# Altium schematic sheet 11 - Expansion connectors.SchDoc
size B; CompanyName: Microchip Technology Inc.; Organization: Microchip Technology; Address1: 2355 West Chandler Blvd.; Address2: Chandler, AZ  85224; Address4: USA; DocumentNumber: 11; SheetNumber: 11; SheetTotal: 13; SheetTitle: Expansion connectors
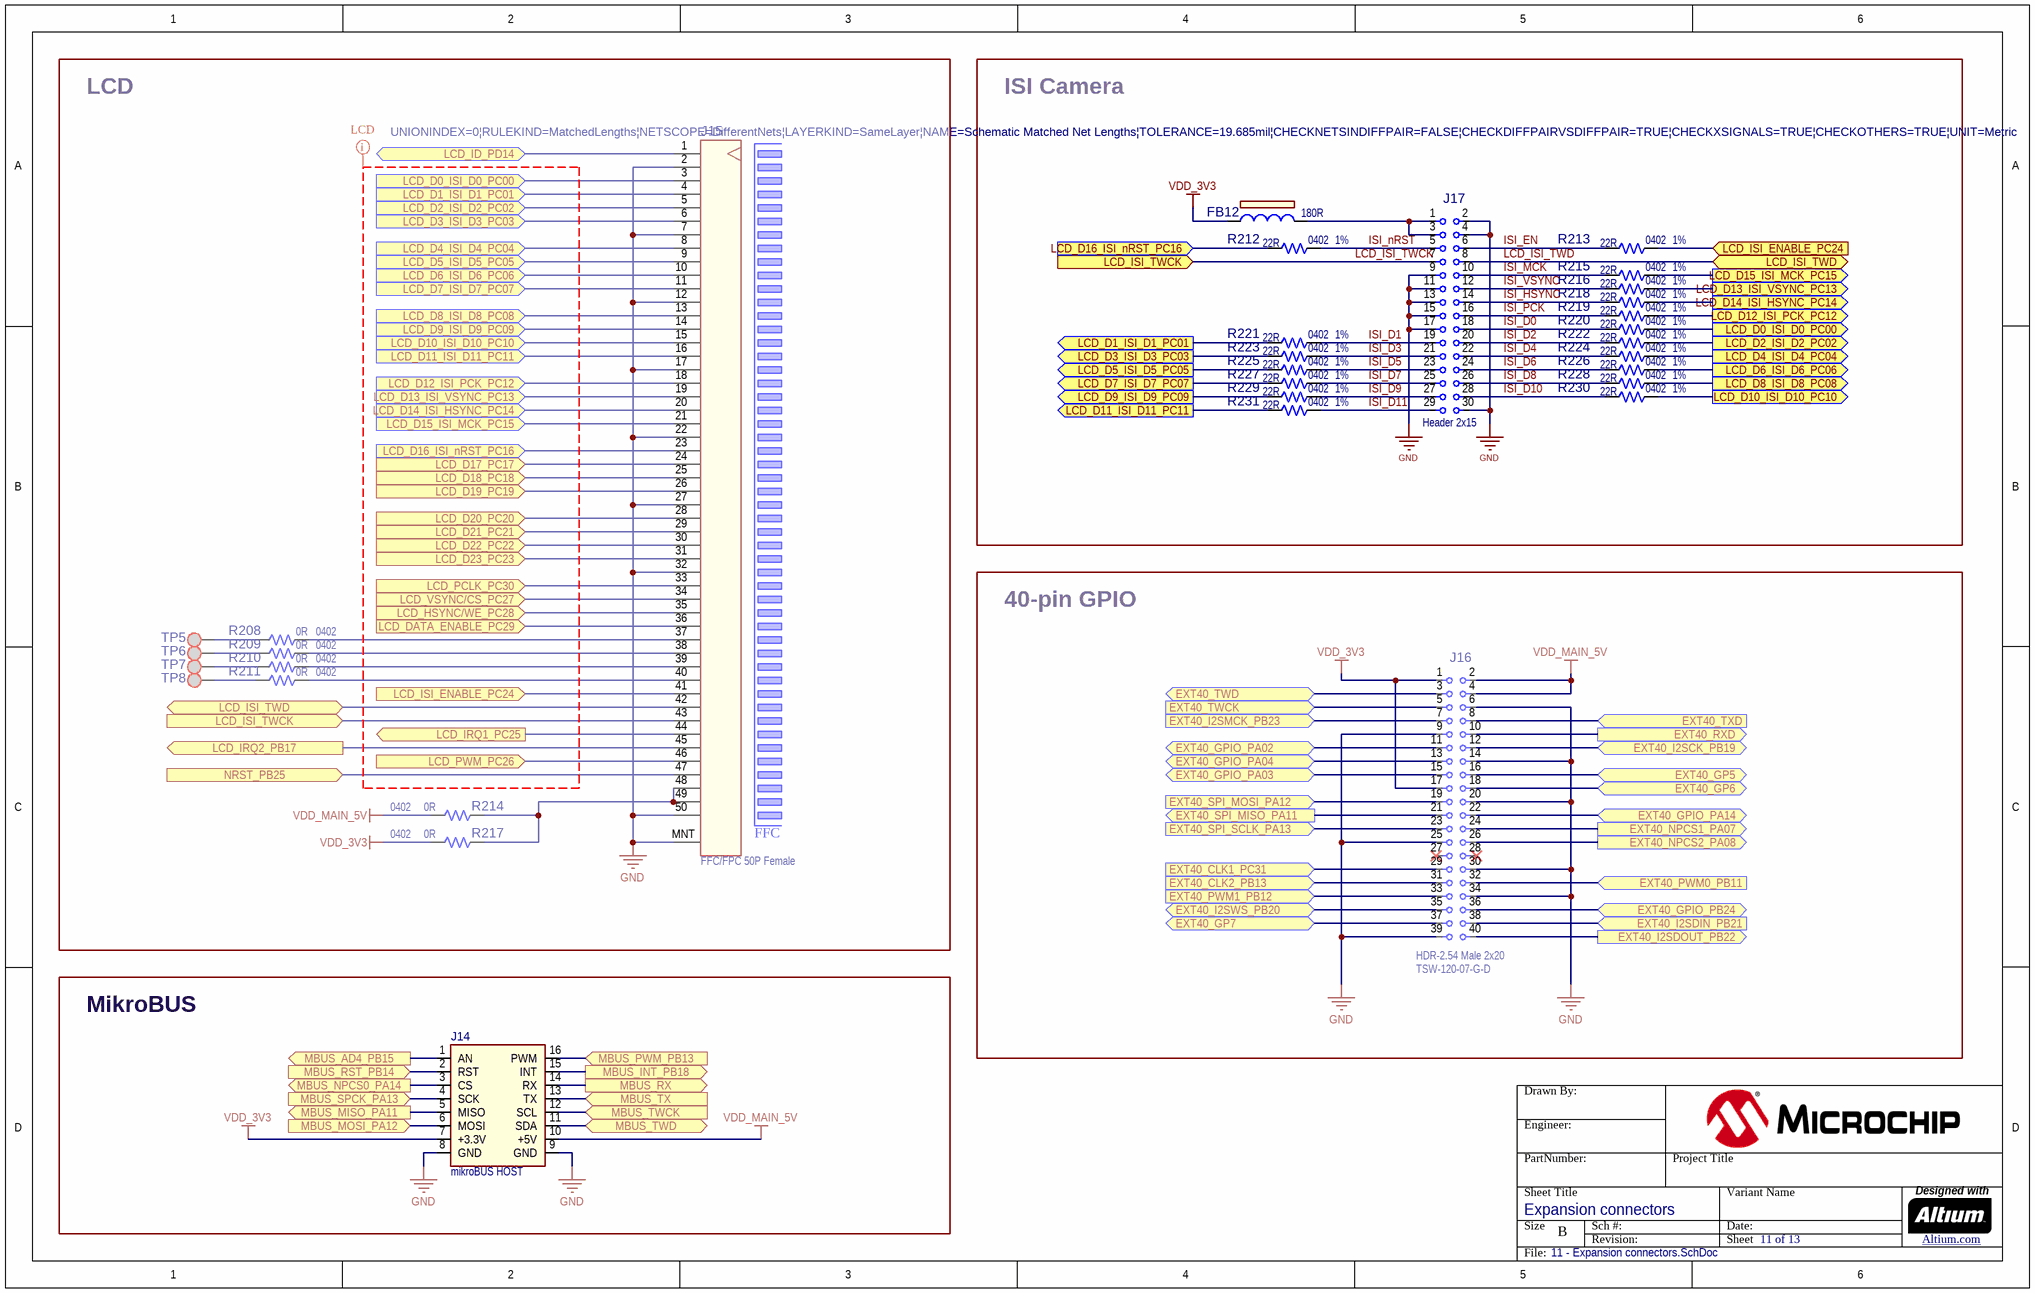
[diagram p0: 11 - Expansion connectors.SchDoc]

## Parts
?  (no value)  (graphical)
FB12  value 180R  [IND_C_0603]  (hidden comment: Ferrite Bead)
J14  value mikroBUS HOST  [SOCKET_mikroBUS_F_2.54_2x8_V_25.4x21]  (hidden comment: SOCKET mikroBUS HOST)
J15  value FFC/FPC 50P Female  [CON_FFC_0.5_FEMALE_1X50_SMD_OMR_XF2M-5015-1A]  (hidden comment: CON FFC 1x50 Mount)
J16  value HDR-2.54 Male 2x20  Manufacturer Part Number 1: TSW-120-07-G-D  [HDR_M_2.54_2x20]  (hidden comment: Header 2x20)
J17  Header 2x15  [HDR_M_2.54_2x15]
R208  value 0R  Package: 0402  [RES_C_0402]  (hidden comment: Resistor)
R209  value 0R  Package: 0402  [RES_C_0402]  (hidden comment: Resistor)
R210  value 0R  Package: 0402  [RES_C_0402]  (hidden comment: Resistor)
R211  value 0R  Package: 0402  [RES_C_0402]  (hidden comment: Resistor)
R212  value 22R  Package: 0402  Tolerance: 1%  [RES_C_0402]  (hidden comment: Resistor)
R213  value 22R  Package: 0402  Tolerance: 1%  [RES_C_0402]  (hidden comment: Resistor)
R214  value 0R  Package: 0402  [RES_C_0402]  (hidden comment: Resistor)
R215  value 22R  Package: 0402  Tolerance: 1%  [RES_C_0402]  (hidden comment: Resistor)
R216  value 22R  Package: 0402  Tolerance: 1%  [RES_C_0402]  (hidden comment: Resistor)
R217  value 0R  Package: 0402  [RES_C_0402]  (hidden comment: Resistor)
R218  value 22R  Package: 0402  Tolerance: 1%  [RES_C_0402]  (hidden comment: Resistor)
R219  value 22R  Package: 0402  Tolerance: 1%  [RES_C_0402]  (hidden comment: Resistor)
R220  value 22R  Package: 0402  Tolerance: 1%  [RES_C_0402]  (hidden comment: Resistor)
R221  value 22R  Package: 0402  Tolerance: 1%  [RES_C_0402]  (hidden comment: Resistor)
R222  value 22R  Package: 0402  Tolerance: 1%  [RES_C_0402]  (hidden comment: Resistor)
R223  value 22R  Package: 0402  Tolerance: 1%  [RES_C_0402]  (hidden comment: Resistor)
R224  value 22R  Package: 0402  Tolerance: 1%  [RES_C_0402]  (hidden comment: Resistor)
R225  value 22R  Package: 0402  Tolerance: 1%  [RES_C_0402]  (hidden comment: Resistor)
R226  value 22R  Package: 0402  Tolerance: 1%  [RES_C_0402]  (hidden comment: Resistor)
R227  value 22R  Package: 0402  Tolerance: 1%  [RES_C_0402]  (hidden comment: Resistor)
R228  value 22R  Package: 0402  Tolerance: 1%  [RES_C_0402]  (hidden comment: Resistor)
R229  value 22R  Package: 0402  Tolerance: 1%  [RES_C_0402]  (hidden comment: Resistor)
R230  value 22R  Package: 0402  Tolerance: 1%  [RES_C_0402]  (hidden comment: Resistor)
R231  value 22R  Package: 0402  Tolerance: 1%  [RES_C_0402]  (hidden comment: Resistor)
TP5  SMD Test Point  [TP_1x1_SMD]  (value not drawn)  (no BOM)
TP6  SMD Test Point  [TP_1x1_SMD]  (value not drawn)  (no BOM)
TP7  SMD Test Point  [TP_1x1_SMD]  (value not drawn)  (no BOM)
TP8  SMD Test Point  [TP_1x1_SMD]  (value not drawn)  (no BOM)

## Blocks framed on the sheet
LCD: J15 R208-R211 R214 R217 TP5-TP8
ISI Camera: FB12 J17 R212 R213 R215 R216 R218-R231
40-pin GPIO: J16
MikroBUS: J14

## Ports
EXT40_CLK1_PC31 (in), EXT40_CLK2_PB13 (in), EXT40_GP5 (bidir), EXT40_GP6 (bidir), EXT40_GP7 (bidir), EXT40_GPIO_PA02 (bidir), EXT40_GPIO_PA03 (bidir), EXT40_GPIO_PA04 (bidir), EXT40_GPIO_PA14 (bidir), EXT40_GPIO_PB24 (bidir), EXT40_I2SCK_PB19 (bidir), EXT40_I2SDIN_PB21 (in), EXT40_I2SDOUT_PB22 (out), EXT40_I2SMCK_PB23 (in), EXT40_I2SWS_PB20 (bidir), EXT40_NPCS1_PA07 (out), EXT40_NPCS2_PA08 (out), EXT40_PWM0_PB11 (in), EXT40_PWM1_PB12 (in), EXT40_RXD (out), EXT40_SPI_MISO_PA11 (out), EXT40_SPI_MOSI_PA12 (in), EXT40_SPI_SCLK_PA13 (in), EXT40_TWCK (in), EXT40_TWD (bidir), EXT40_TXD (in), LCD_D0_ISI_D0_PC00 (in), LCD_D0_ISI_D0_PC00 (out), LCD_D1_ISI_D1_PC01 (in), LCD_D1_ISI_D1_PC01 (out), LCD_D2_ISI_D2_PC02 (in), LCD_D2_ISI_D2_PC02 (out), LCD_D3_ISI_D3_PC03 (in), LCD_D3_ISI_D3_PC03 (out), LCD_D4_ISI_D4_PC04 (in), LCD_D4_ISI_D4_PC04 (out), LCD_D5_ISI_D5_PC05 (in), LCD_D5_ISI_D5_PC05 (out), LCD_D6_ISI_D6_PC06 (in), LCD_D6_ISI_D6_PC06 (out), LCD_D7_ISI_D7_PC07 (in), LCD_D7_ISI_D7_PC07 (out), LCD_D8_ISI_D8_PC08 (in), LCD_D8_ISI_D8_PC08 (out), LCD_D9_ISI_D9_PC09 (in), LCD_D9_ISI_D9_PC09 (out), LCD_D10_ISI_D10_PC10 (in), LCD_D10_ISI_D10_PC10 (out), LCD_D11_ISI_D11_PC11 (in), LCD_D11_ISI_D11_PC11 (out), LCD_D12_ISI_PCK_PC12 (in), LCD_D12_ISI_PCK_PC12 (out), LCD_D13_ISI_VSYNC_PC13 (in), LCD_D13_ISI_VSYNC_PC13 (out), LCD_D14_ISI_HSYNC_PC14 (in), LCD_D14_ISI_HSYNC_PC14 (out), LCD_D15_ISI_MCK_PC15 (in), LCD_D15_ISI_MCK_PC15 (out), LCD_D16_ISI_nRST_PC16 (in), LCD_D17_PC17 (in), LCD_D18_PC18 (in), LCD_D19_PC19 (in), LCD_D20_PC20 (in), LCD_D21_PC21 (in), LCD_D22_PC22 (in), LCD_D23_PC23 (in), LCD_DATA_ENABLE_PC29 (in), LCD_HSYNC/WE_PC28 (in), LCD_ID_PD14 (bidir), LCD_IRQ1_PC25 (out), LCD_IRQ2_PB17 (out), LCD_ISI_ENABLE_PC24 (in), LCD_ISI_TWCK (in), LCD_ISI_TWD (bidir), LCD_PCLK_PC30 (in), LCD_PWM_PC26 (in), LCD_VSYNC/CS_PC27 (in), MBUS_AD4_PB15 (out), MBUS_INT_PB18 (out), MBUS_MISO_PA11 (out), MBUS_MOSI_PA12 (in), MBUS_NPCS0_PA14 (out), MBUS_PWM_PB13 (in), MBUS_RST_PB14 (in), MBUS_RX (out), MBUS_SPCK_PA13 (in), MBUS_TWCK (in), MBUS_TWD (bidir), MBUS_TX (in), NRST_PB25 (in)

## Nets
GND: J14.8(GND) J14.9(GND) J15.2 J15.7 J15.12 J15.17 J15.22 J15.27 J15.32 J15.50 J15.MNT J16.6 J16.9 J16.14 J16.20 J16.25 J16.30 J16.34 J16.39 J17.2 J17.4 J17.9 J17.11 J17.13 J17.15 J17.17 J17.30
VDD_3V3: FB12.1 J14.7(+3.3V) J16.1 J16.17 R217.2
VDD_MAIN_5V: J14.10(+5V) J16.2 J16.4 R214.2
EXT40_CLK1_PC31: J16.29 ; port EXT40_CLK1_PC31
EXT40_CLK2_PB13: J16.31 ; port EXT40_CLK2_PB13
EXT40_GP5: J16.16 ; port EXT40_GP5
EXT40_GP6: J16.18 ; port EXT40_GP6
EXT40_GP7: J16.37 ; port EXT40_GP7
EXT40_GPIO_PA02: J16.11 ; port EXT40_GPIO_PA02
EXT40_GPIO_PA03: J16.15 ; port EXT40_GPIO_PA03
EXT40_GPIO_PA04: J16.13 ; port EXT40_GPIO_PA04
EXT40_GPIO_PA14: J16.22 ; port EXT40_GPIO_PA14
EXT40_GPIO_PB24: J16.36 ; port EXT40_GPIO_PB24
EXT40_I2SCK_PB19: J16.12 ; port EXT40_I2SCK_PB19
EXT40_I2SDIN_PB21: J16.38 ; port EXT40_I2SDIN_PB21
EXT40_I2SDOUT_PB22: J16.40 ; port EXT40_I2SDOUT_PB22
EXT40_I2SMCK_PB23: J16.7 ; port EXT40_I2SMCK_PB23
EXT40_I2SWS_PB20: J16.35 ; port EXT40_I2SWS_PB20
EXT40_NPCS1_PA07: J16.24 ; port EXT40_NPCS1_PA07
EXT40_NPCS2_PA08: J16.26 ; port EXT40_NPCS2_PA08
EXT40_PWM0_PB11: J16.32 ; port EXT40_PWM0_PB11
EXT40_PWM1_PB12: J16.33 ; port EXT40_PWM1_PB12
EXT40_RXD: J16.10 ; port EXT40_RXD
EXT40_SPI_MISO_PA11: J16.21 ; port EXT40_SPI_MISO_PA11
EXT40_SPI_MOSI_PA12: J16.19 ; port EXT40_SPI_MOSI_PA12
EXT40_SPI_SCLK_PA13: J16.23 ; port EXT40_SPI_SCLK_PA13
EXT40_TWCK: J16.5 ; port EXT40_TWCK
EXT40_TWD: J16.3 ; port EXT40_TWD
EXT40_TXD: J16.8 ; port EXT40_TXD
ISI_D0: J17.18 R220.1
ISI_D1: J17.19 R221.2
ISI_D2: J17.20 R222.1
ISI_D3: J17.21 R223.2
ISI_D4: J17.22 R224.1
ISI_D5: J17.23 R225.2
ISI_D6: J17.24 R226.1
ISI_D7: J17.25 R227.2
ISI_D8: J17.26 R228.1
ISI_D9: J17.27 R229.2
ISI_D10: J17.28 R230.1
ISI_D11: J17.29 R231.2
ISI_EN: J17.6 R213.1
ISI_HSYNC: J17.14 R218.1
ISI_MCK: J17.10 R215.1
ISI_nRST: J17.5 R212.2
ISI_PCK: J17.16 R219.1
ISI_VSYNC: J17.12 R216.1
LCD_D0_ISI_D0_PC00: J15.3 R220.2 ; port LCD_D0_ISI_D0_PC00
LCD_D1_ISI_D1_PC01: J15.4 R221.1 ; port LCD_D1_ISI_D1_PC01
LCD_D2_ISI_D2_PC02: J15.5 R222.2 ; port LCD_D2_ISI_D2_PC02
LCD_D3_ISI_D3_PC03: J15.6 R223.1 ; port LCD_D3_ISI_D3_PC03
LCD_D4_ISI_D4_PC04: J15.8 R224.2 ; port LCD_D4_ISI_D4_PC04
LCD_D5_ISI_D5_PC05: J15.9 R225.1 ; port LCD_D5_ISI_D5_PC05
LCD_D6_ISI_D6_PC06: J15.10 R226.2 ; port LCD_D6_ISI_D6_PC06
LCD_D7_ISI_D7_PC07: J15.11 R227.1 ; port LCD_D7_ISI_D7_PC07
LCD_D8_ISI_D8_PC08: J15.13 R228.2 ; port LCD_D8_ISI_D8_PC08
LCD_D9_ISI_D9_PC09: J15.14 R229.1 ; port LCD_D9_ISI_D9_PC09
LCD_D10_ISI_D10_PC10: J15.15 R230.2 ; port LCD_D10_ISI_D10_PC10
LCD_D11_ISI_D11_PC11: J15.16 R231.1 ; port LCD_D11_ISI_D11_PC11
LCD_D12_ISI_PCK_PC12: J15.18 R219.2 ; port LCD_D12_ISI_PCK_PC12
LCD_D13_ISI_VSYNC_PC13: J15.19 R216.2 ; port LCD_D13_ISI_VSYNC_PC13
LCD_D14_ISI_HSYNC_PC14: J15.20 R218.2 ; port LCD_D14_ISI_HSYNC_PC14
LCD_D15_ISI_MCK_PC15: J15.21 R215.2 ; port LCD_D15_ISI_MCK_PC15
LCD_D16_ISI_nRST_PC16: J15.23 R212.1 ; port LCD_D16_ISI_nRST_PC16
LCD_D17_PC17: J15.24 ; port LCD_D17_PC17
LCD_D18_PC18: J15.25 ; port LCD_D18_PC18
LCD_D19_PC19: J15.26 ; port LCD_D19_PC19
LCD_D20_PC20: J15.28 ; port LCD_D20_PC20
LCD_D21_PC21: J15.29 ; port LCD_D21_PC21
LCD_D22_PC22: J15.30 ; port LCD_D22_PC22
LCD_D23_PC23: J15.31 ; port LCD_D23_PC23
LCD_DATA_ENABLE_PC29: J15.36 ; port LCD_DATA_ENABLE_PC29
LCD_HSYNC/WE_PC28: J15.35 ; port LCD_HSYNC/WE_PC28
LCD_ID_PD14: J15.1 ; port LCD_ID_PD14
LCD_IRQ1_PC25: J15.44 ; port LCD_IRQ1_PC25
LCD_IRQ2_PB17: J15.45 ; port LCD_IRQ2_PB17
LCD_ISI_ENABLE_PC24: J15.41 R213.2 ; port LCD_ISI_ENABLE_PC24
LCD_ISI_TWCK: J15.43 J17.7 ; port LCD_ISI_TWCK
LCD_ISI_TWD: J15.42 J17.8 ; port LCD_ISI_TWD
LCD_PCLK_PC30: J15.33 ; port LCD_PCLK_PC30
LCD_PWM_PC26: J15.46 ; port LCD_PWM_PC26
LCD_VSYNC/CS_PC27: J15.34 ; port LCD_VSYNC/CS_PC27
MBUS_AD4_PB15: J14.1(AN) ; port MBUS_AD4_PB15
MBUS_INT_PB18: J14.15(INT) ; port MBUS_INT_PB18
MBUS_MISO_PA11: J14.5(MISO) ; port MBUS_MISO_PA11
MBUS_MOSI_PA12: J14.6(MOSI) ; port MBUS_MOSI_PA12
MBUS_NPCS0_PA14: J14.3(CS) ; port MBUS_NPCS0_PA14
MBUS_PWM_PB13: J14.16(PWM) ; port MBUS_PWM_PB13
MBUS_RST_PB14: J14.2(RST) ; port MBUS_RST_PB14
MBUS_RX: J14.14(RX) ; port MBUS_RX
MBUS_SPCK_PA13: J14.4(SCK) ; port MBUS_SPCK_PA13
MBUS_TWCK: J14.12(SCL) ; port MBUS_TWCK
MBUS_TWD: J14.11(SDA) ; port MBUS_TWD
MBUS_TX: J14.13(TX) ; port MBUS_TX
NRST_PB25: J15.47 ; port NRST_PB25
NetFB12_2: FB12.2 J17.1 J17.3
NetJ15_37: J15.37 R208.2
NetJ15_38: J15.38 R209.2
NetJ15_39: J15.39 R210.2
NetJ15_40: J15.40 R211.2
NetJ15_48: J15.48 J15.49 R214.1 R217.1
NetR208_1: R208.1 TP5.1
NetR209_1: R209.1 TP6.1
NetR210_1: R210.1 TP7.1
NetR211_1: R211.1 TP8.1

Not connected (* = marked no-connect by the designer): J16 27* 28*

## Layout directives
net class LCD-DATA; rule Matched Net Lengths [Tolerance = 0.5mm]: (no net found under the mark)

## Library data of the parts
? = Title Block B
FB12 = IND1453: FERRITE 180R 1.5A SMD 0603; Manufacturer 1: Murata Electronics North America; Manufacturer Part Number 1: BLM18PG181SN1D; Dev Tools Status: Production; Owner: Dragos Danaila; DCR: 0.09R; Test Frequency: 100MHz; Populated: YES
J14 = SKT1042: Manufacturer 1: Sullins Connector Solutions; Manufacturer Part Number 1: PPTC081LFBN-RC; Description_: SOCKET mikroBUS HOST DIP 16 TH; Dev Tools Status: Production; Owner: Stephen Humberd; Populated: YES
J15 = CON1372: Manufacturer 1: Omron Electronics Inc-EMC Div; Manufacturer Part Number 1: XF2M-5015-1A; Description_: CON FFC/FPC XF2M 0.5mm 50P Female SMD R/A; Dev Tools Status: Production; Owner: Tad Ahlvers; Current: 0.5A; Populated: YES
J16 = CON0153: Manufacturer 1: Samtec; Description_: CON HDR-2.54 Male 2x20 Gold 5.84MH TH VERT; Dev Tools Status: Production; Owner: Stephen Humberd; Populated: YES
J17 = CON1580: Manufacturer 1: Wurth Electronics Inc.; Manufacturer Part Number 1: 61303021121; Description_: 30 Positions Header, Unshrouded, Breakaway Connector 0.100" (2.54mm) Through Hole Gold; Dev Tools Status: Production; Owner: Tim Moffat; Populated: YES
R208-R211 R217 = RSMT1040: Manufacturer 1: Yageo; Manufacturer Part Number 1: RC0402JR-070RL; Description_: RES TKF 0R 1/16W SMD 0402; Dev Tools Status: Production; Power: 1/16W; Owner: Sompoch Loboonlert; Populated: DNP
R212 R213 R215 R216 R218-R231 = RES1474: Manufacturer 1: Panasonic Electronic Components; Manufacturer Part Number 1: ERJ-2RKF22R0X; Description_: RES TKF 22R 1% 1/20W SMD 0402; Dev Tools Status: Production; Temperature Coeffcient: 100ppm/C; Circuit Type: Isolated; Power: 1/10W; Owner: Mike Ragsdale; Populated: YES
R214 = RSMT1040: Manufacturer 1: Yageo; Manufacturer Part Number 1: RC0402JR-070RL; Description_: RES TKF 0R 1/16W SMD 0402; Dev Tools Status: Production; Power: 1/16W; Owner: Sompoch Loboonlert; Populated: Yes
TP5-TP8 = TEST-POINT: Test Point pad 1.00mm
